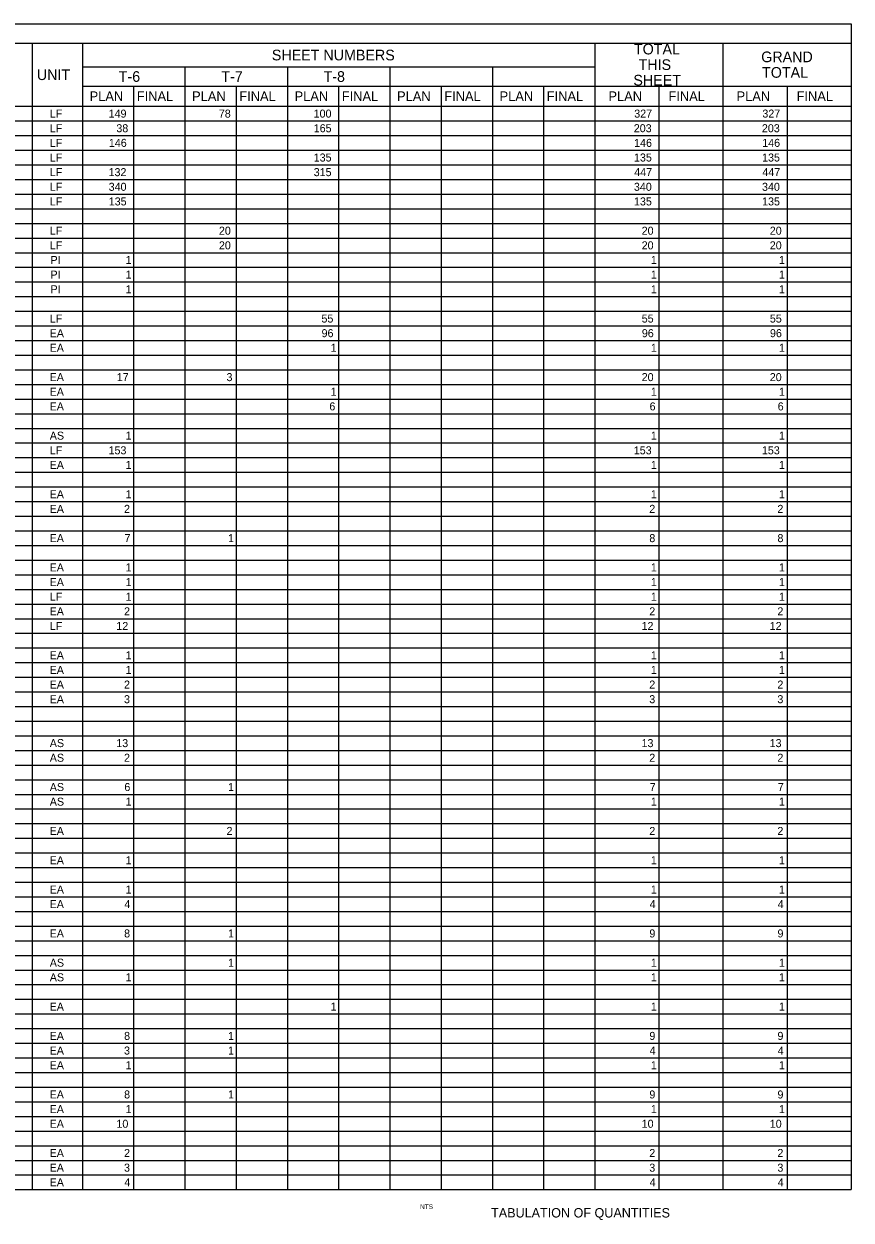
# Model space of a CAD drawing. Extents: x 0.1 to 15.3, y -0.2 to 9.6.
# Drawn here: x 8.54 to 15.31, y -0.16 to 9.64 of the extents above; entities that cross this region are included whole.
import ezdxf

# ---------------------------------------------------------------- set-up
doc = ezdxf.new("R2010")
doc.units = 0
for name, color, linetype in [('Default', 7, 'Continuous'), ('SumBoxBorder_dp', 7, 'Continuous'), ('SumBoxLines_dp', 7, 'Continuous'), ('SumBoxLinesMin_dp', 7, 'Continuous'), ('TextLabel', 7, 'Continuous'), ('TextMisc', 7, 'Continuous')]:
    doc.layers.add(name, color=color, linetype=linetype)

msp = doc.modelspace()

# ---------------------------------------------------------------- linework, layer by layer
at = {"layer": 'SumBoxBorder_dp'}
for p, q in [((0.1195, 9.6404), (15.3145, 9.6404)), ((15.3145, 9.6404), (15.3145, 0.0854)), ((0.1195, 9.4829), (15.3145, 9.4829)), ((0.1195, 9.4829), (15.3145, 9.4829)), ((0.1195, 0.0854), (15.3145, 0.0854))]:
    msp.add_line(p, q, dxfattribs=at)
at = {"layer": 'SumBoxLines_dp'}
for p, q in [((8.602, 9.4829), (8.602, 4.4054)), ((8.602, 9.4829), (8.602, 0.0854)), ((9.0145, 9.4829), (9.0145, 9.1304)), ((9.0145, 9.4829), (9.0145, 0.0854)), ((13.2145, 9.4829), (13.2145, 0.0854)), ((13.2145, 9.4829), (13.2145, 0.0854)), ((14.2645, 9.4829), (14.2645, 0.0854)), ((9.0145, 9.2879), (13.2145, 9.2879)), ((9.0145, 9.2879), (13.2145, 9.2879)), ((9.8545, 9.2879), (9.8545, 0.0854)), ((9.8545, 9.2879), (9.8545, 0.0854)), ((10.6945, 9.2879), (10.6945, 0.0854)), ((10.6945, 9.2879), (10.6945, 9.1304)), ((11.5345, 9.2879), (11.5345, 0.0854)), ((11.5345, 9.2879), (11.5345, 0.0854)), ((12.3745, 9.2879), (12.3745, 8.8454)), ((12.3745, 9.2879), (12.3745, 0.0854)), ((9.0145, 9.1304), (15.3145, 9.1304)), ((11.5345, 9.1304), (15.3145, 9.1304)), ((14.2645, 9.1304), (14.2645, 8.8454)), ((0.1195, 8.9654), (15.3145, 8.9654)), ((0.1195, 8.9654), (15.3145, 8.9654)), ((9.0145, 8.9654), (9.0145, 0.0854)), ((10.6945, 8.9654), (10.6945, 0.0854)), ((12.3745, 8.7254), (12.3745, 0.0854)), ((14.2645, 8.7254), (14.2645, 0.0854)), ((8.602, 4.2854), (8.602, 0.0854))]:
    msp.add_line(p, q, dxfattribs=at)
at = {"layer": 'SumBoxLinesMin_dp'}
for p, q in [((9.4345, 9.1304), (9.4345, 8.8454)), ((9.4345, 9.1304), (9.4345, 0.0854)), ((10.2745, 9.1304), (10.2745, 8.8454)), ((10.2745, 9.1304), (10.2745, 0.0854)), ((10.6945, 9.1304), (10.6945, 8.9654)), ((11.1145, 9.1304), (11.1145, 8.8454)), ((11.1145, 9.1304), (11.1145, 0.0854)), ((11.9545, 9.1304), (11.9545, 0.0854)), ((11.9545, 9.1304), (11.9545, 0.0854)), ((12.7945, 9.1304), (12.7945, 0.0854)), ((12.7945, 9.1304), (12.7945, 0.0854)), ((13.7395, 9.1304), (13.7395, 0.0854)), ((13.7395, 9.1304), (13.7395, 0.0854)), ((14.7895, 9.1304), (14.7895, 0.0854)), ((14.7895, 9.1304), (14.7895, 0.0854)), ((0.1195, 8.8454), (15.3145, 8.8454)), ((0.1195, 8.8454), (15.3145, 8.8454)), ((12.3745, 8.8454), (12.3745, 8.7254)), ((14.2645, 8.8454), (14.2645, 8.7254)), ((0.1195, 8.7254), (15.3145, 8.7254)), ((0.1195, 8.7254), (15.3145, 8.7254)), ((9.4345, 8.7254), (9.4345, 0.0854)), ((10.2745, 8.7254), (10.2745, 0.0854)), ((11.1145, 8.7254), (11.1145, 0.0854)), ((0.1195, 8.6054), (15.3145, 8.6054)), ((0.1195, 8.6054), (15.3145, 8.6054)), ((0.1195, 8.4854), (15.3145, 8.4854)), ((0.1195, 8.4854), (15.3145, 8.4854)), ((0.1195, 8.3654), (15.3145, 8.3654)), ((0.1195, 8.3654), (15.3145, 8.3654)), ((0.1195, 8.2454), (15.3145, 8.2454)), ((0.1195, 8.2454), (15.3145, 8.2454)), ((0.1195, 8.1254), (15.3145, 8.1254)), ((0.1195, 8.1254), (15.3145, 8.1254)), ((0.1195, 8.0054), (15.3145, 8.0054)), ((0.1195, 8.0054), (15.3145, 8.0054)), ((0.1195, 7.8854), (15.3145, 7.8854)), ((0.1195, 7.8854), (15.3145, 7.8854)), ((0.1195, 7.7654), (15.3145, 7.7654)), ((0.1195, 7.7654), (15.3145, 7.7654)), ((0.1195, 7.6454), (15.3145, 7.6454)), ((0.1195, 7.6454), (15.3145, 7.6454)), ((0.1195, 7.5254), (15.3145, 7.5254)), ((0.1195, 7.5254), (15.3145, 7.5254)), ((0.1195, 7.4054), (15.3145, 7.4054)), ((0.1195, 7.4054), (15.3145, 7.4054)), ((0.1195, 7.2854), (15.3145, 7.2854)), ((0.1195, 7.2854), (15.3145, 7.2854)), ((0.1195, 7.1654), (15.3145, 7.1654)), ((0.1195, 7.1654), (15.3145, 7.1654)), ((0.1195, 7.0454), (15.3145, 7.0454)), ((0.1195, 7.0454), (15.3145, 7.0454)), ((0.1195, 6.9254), (15.3145, 6.9254)), ((0.1195, 6.9254), (15.3145, 6.9254)), ((0.1195, 6.8054), (15.3145, 6.8054)), ((0.1195, 6.8054), (15.3145, 6.8054)), ((0.1195, 6.6854), (15.3145, 6.6854)), ((0.1195, 6.6854), (15.3145, 6.6854)), ((0.1195, 6.5654), (15.3145, 6.5654)), ((0.1195, 6.5654), (15.3145, 6.5654)), ((0.1195, 6.4454), (15.3145, 6.4454)), ((0.1195, 6.4454), (15.3145, 6.4454)), ((0.1195, 6.3254), (15.3145, 6.3254)), ((0.1195, 6.3254), (15.3145, 6.3254)), ((0.1195, 6.2054), (15.3145, 6.2054)), ((0.1195, 6.2054), (15.3145, 6.2054)), ((0.1195, 6.0854), (15.3145, 6.0854)), ((0.1195, 6.0854), (15.3145, 6.0854)), ((0.1195, 5.9654), (15.3145, 5.9654)), ((0.1195, 5.9654), (15.3145, 5.9654)), ((0.1195, 5.8454), (15.3145, 5.8454)), ((0.1195, 5.8454), (15.3145, 5.8454)), ((0.1195, 5.7254), (15.3145, 5.7254)), ((0.1195, 5.7254), (15.3145, 5.7254)), ((0.1195, 5.6054), (15.3145, 5.6054)), ((0.1195, 5.6054), (15.3145, 5.6054)), ((0.1195, 5.4854), (15.3145, 5.4854)), ((0.1195, 5.4854), (15.3145, 5.4854)), ((0.1195, 5.3654), (15.3145, 5.3654)), ((0.1195, 5.3654), (15.3145, 5.3654)), ((0.1195, 5.2454), (15.3145, 5.2454)), ((0.1195, 5.2454), (15.3145, 5.2454)), ((0.1195, 5.1254), (15.3145, 5.1254)), ((0.1195, 5.1254), (15.3145, 5.1254)), ((0.1195, 5.0054), (15.3145, 5.0054)), ((0.1195, 5.0054), (15.3145, 5.0054)), ((0.1195, 4.8854), (15.3145, 4.8854)), ((0.1195, 4.8854), (15.3145, 4.8854)), ((0.1195, 4.7654), (15.3145, 4.7654)), ((0.1195, 4.7654), (15.3145, 4.7654)), ((0.1195, 4.6454), (15.3145, 4.6454)), ((0.1195, 4.6454), (15.3145, 4.6454)), ((0.1195, 4.5254), (15.3145, 4.5254)), ((0.1195, 4.5254), (15.3145, 4.5254)), ((0.1195, 4.4054), (15.3145, 4.4054)), ((0.1195, 4.4054), (15.3145, 4.4054)), ((0.1195, 4.2854), (15.3145, 4.2854)), ((8.602, 4.2854), (15.3145, 4.2854)), ((0.1195, 4.1654), (15.3145, 4.1654)), ((0.1195, 4.1654), (15.3145, 4.1654)), ((0.1195, 4.0454), (15.3145, 4.0454)), ((0.1195, 4.0454), (15.3145, 4.0454)), ((0.1195, 3.9254), (15.3145, 3.9254)), ((0.1195, 3.9254), (15.3145, 3.9254)), ((0.1195, 3.8054), (15.3145, 3.8054)), ((0.1195, 3.8054), (15.3145, 3.8054)), ((0.1195, 3.6854), (15.3145, 3.6854)), ((0.1195, 3.6854), (15.3145, 3.6854)), ((0.1195, 3.5654), (15.3145, 3.5654)), ((0.1195, 3.5654), (15.3145, 3.5654)), ((0.1195, 3.4454), (15.3145, 3.4454)), ((0.1195, 3.4454), (15.3145, 3.4454)), ((0.1195, 3.3254), (15.3145, 3.3254)), ((0.1195, 3.3254), (15.3145, 3.3254)), ((0.1195, 3.2054), (15.3145, 3.2054)), ((0.1195, 3.2054), (15.3145, 3.2054)), ((0.1195, 3.0854), (15.3145, 3.0854)), ((0.1195, 3.0854), (15.3145, 3.0854)), ((0.1195, 2.9654), (15.3145, 2.9654)), ((0.1195, 2.9654), (15.3145, 2.9654)), ((0.1195, 2.8454), (15.3145, 2.8454)), ((0.1195, 2.8454), (15.3145, 2.8454)), ((0.1195, 2.7254), (15.3145, 2.7254)), ((0.1195, 2.7254), (15.3145, 2.7254)), ((0.1195, 2.6054), (15.3145, 2.6054)), ((0.1195, 2.6054), (15.3145, 2.6054)), ((0.1195, 2.4854), (15.3145, 2.4854)), ((0.1195, 2.4854), (15.3145, 2.4854)), ((0.1195, 2.3654), (15.3145, 2.3654)), ((0.1195, 2.3654), (15.3145, 2.3654)), ((0.1195, 2.2454), (15.3145, 2.2454)), ((0.1195, 2.2454), (15.3145, 2.2454)), ((0.1195, 2.1254), (15.3145, 2.1254)), ((9.0145, 2.1254), (9.4345, 2.1254)), ((9.8545, 2.1254), (10.2745, 2.1254)), ((13.2145, 2.1254), (13.7395, 2.1254)), ((14.2645, 2.1254), (14.7895, 2.1254)), ((0.1195, 2.0054), (15.3145, 2.0054)), ((9.0145, 2.0054), (9.4345, 2.0054)), ((9.8545, 2.0054), (10.2745, 2.0054)), ((13.2145, 2.0054), (13.7395, 2.0054)), ((14.2645, 2.0054), (14.7895, 2.0054)), ((0.1195, 1.8854), (15.3145, 1.8854)), ((9.0145, 1.8854), (9.4345, 1.8854)), ((9.8545, 1.8854), (10.2745, 1.8854)), ((13.2145, 1.8854), (13.7395, 1.8854)), ((14.2645, 1.8854), (14.7895, 1.8854)), ((0.1195, 1.7654), (15.3145, 1.7654)), ((9.0145, 1.7654), (9.4345, 1.7654)), ((9.8545, 1.7654), (10.2745, 1.7654)), ((13.2145, 1.7654), (13.7395, 1.7654)), ((14.2645, 1.7654), (14.7895, 1.7654)), ((0.1195, 1.6454), (15.3145, 1.6454)), ((9.0145, 1.6454), (9.4345, 1.6454)), ((9.8545, 1.6454), (10.2745, 1.6454)), ((13.2145, 1.6454), (13.7395, 1.6454)), ((14.2645, 1.6454), (14.7895, 1.6454)), ((0.1195, 1.5254), (15.3145, 1.5254)), ((9.0145, 1.5254), (9.4345, 1.5254)), ((9.8545, 1.5254), (10.2745, 1.5254)), ((13.2145, 1.5254), (13.7395, 1.5254)), ((14.2645, 1.5254), (14.7895, 1.5254)), ((0.1195, 1.4054), (15.3145, 1.4054)), ((9.0145, 1.4054), (9.4345, 1.4054)), ((9.8545, 1.4054), (10.2745, 1.4054)), ((13.2145, 1.4054), (13.7395, 1.4054)), ((14.2645, 1.4054), (14.7895, 1.4054)), ((0.1195, 1.2854), (15.3145, 1.2854)), ((9.0145, 1.2854), (9.4345, 1.2854)), ((9.8545, 1.2854), (10.2745, 1.2854)), ((13.2145, 1.2854), (13.7395, 1.2854)), ((14.2645, 1.2854), (14.7895, 1.2854)), ((0.1195, 1.1654), (15.3145, 1.1654)), ((9.0145, 1.1654), (9.4345, 1.1654)), ((9.8545, 1.1654), (10.2745, 1.1654)), ((13.2145, 1.1654), (13.7395, 1.1654)), ((14.2645, 1.1654), (14.7895, 1.1654)), ((0.1195, 1.0454), (15.3145, 1.0454)), ((9.0145, 1.0454), (9.4345, 1.0454)), ((9.8545, 1.0454), (10.2745, 1.0454)), ((13.2145, 1.0454), (13.7395, 1.0454)), ((14.2645, 1.0454), (14.7895, 1.0454)), ((0.1195, 0.9254), (15.3145, 0.9254)), ((9.0145, 0.9254), (9.4345, 0.9254)), ((9.8545, 0.9254), (10.2745, 0.9254)), ((13.2145, 0.9254), (13.7395, 0.9254)), ((14.2645, 0.9254), (14.7895, 0.9254)), ((0.1195, 0.8054), (15.3145, 0.8054)), ((9.0145, 0.8054), (9.4345, 0.8054)), ((9.8545, 0.8054), (10.2745, 0.8054)), ((13.2145, 0.8054), (13.7395, 0.8054)), ((14.2645, 0.8054), (14.7895, 0.8054)), ((0.1195, 0.6854), (15.3145, 0.6854)), ((9.0145, 0.6854), (9.4345, 0.6854)), ((9.8545, 0.6854), (10.2745, 0.6854)), ((13.2145, 0.6854), (13.7395, 0.6854)), ((14.2645, 0.6854), (14.7895, 0.6854)), ((0.1195, 0.5654), (15.3145, 0.5654)), ((9.0145, 0.5654), (9.4345, 0.5654)), ((9.8545, 0.5654), (10.2745, 0.5654)), ((13.2145, 0.5654), (13.7395, 0.5654)), ((14.2645, 0.5654), (14.7895, 0.5654)), ((0.1195, 0.4454), (15.3145, 0.4454)), ((9.0145, 0.4454), (9.4345, 0.4454)), ((9.8545, 0.4454), (10.2745, 0.4454)), ((13.2145, 0.4454), (13.7395, 0.4454)), ((14.2645, 0.4454), (14.7895, 0.4454)), ((0.1195, 0.3254), (15.3145, 0.3254)), ((9.0145, 0.3254), (9.4345, 0.3254)), ((9.8545, 0.3254), (10.2745, 0.3254)), ((13.2145, 0.3254), (13.7395, 0.3254)), ((14.2645, 0.3254), (14.7895, 0.3254)), ((0.1195, 0.2054), (15.3145, 0.2054)), ((13.2145, 0.2054), (13.7395, 0.2054)), ((14.2645, 0.2054), (14.7895, 0.2054))]:
    msp.add_line(p, q, dxfattribs=at)

# ---------------------------------------------------------------- texts
at = {"layer": 'Default'}
msp.add_text('TABULATION OF QUANTITIES', height=0.0771, dxfattribs=at).set_placement((12.364, -0.143))
at = {"layer": 'TextLabel'}
for s, height, p in [('SHEET NUMBERS', 0.0875, (10.567, 9.3417)), ('TOTAL', 0.0875, (13.5349, 9.3904)), ('GRAND', 0.0875, (14.5781, 9.3267)), ('THIS', 0.0875, (13.5731, 9.2629)), ('UNIT', 0.0875, (8.6411, 9.1804)), ('T-6', 0.0875, (9.3123, 9.1654)), ('T-7', 0.0875, (10.153, 9.1654)), ('T-8', 0.0875, (10.9908, 9.1654)), ('SHEET', 0.0875, (13.53, 9.1354)), ('TOTAL', 0.0875, (14.5849, 9.1992)), ('PLAN', 0.07875, (9.0735, 9.0085)), ('FINAL', 0.07875, (9.4604, 9.0085)), ('PLAN', 0.07875, (9.9135, 9.0085)), ('FINAL', 0.07875, (10.3004, 9.0085)), ('PLAN', 0.07875, (10.7535, 9.0085)), ('FINAL', 0.07875, (11.1404, 9.0085)), ('PLAN', 0.07875, (11.5935, 9.0085)), ('FINAL', 0.07875, (11.9804, 9.0085)), ('PLAN', 0.07875, (12.4335, 9.0085)), ('FINAL', 0.07875, (12.8204, 9.0085)), ('PLAN', 0.07875, (13.326, 9.0085)), ('FINAL', 0.07875, (13.8179, 9.0085)), ('PLAN', 0.07875, (14.376, 9.0085)), ('FINAL', 0.07875, (14.8679, 9.0085)), ('LF', 0.06563, (8.7478, 8.8726)), ('149', 0.06563, (9.2293, 8.8726)), ('78', 0.06563, (10.1325, 8.8726)), ('100', 0.06563, (10.9096, 8.8726)), ('327', 0.06563, (13.5373, 8.8726)), ('327', 0.06563, (14.5873, 8.8726)), ('LF', 0.06563, (8.7478, 8.7526)), ('38', 0.06563, (9.2925, 8.7526)), ('165', 0.06563, (10.9102, 8.7526)), ('203', 0.06563, (13.5335, 8.7526)), ('203', 0.06563, (14.5835, 8.7526)), ('LF', 0.06563, (8.7478, 8.6326)), ('146', 0.06563, (9.2312, 8.6326)), ('146', 0.06563, (13.5362, 8.6326)), ('146', 0.06563, (14.5862, 8.6326)), ('LF', 0.06563, (8.7478, 8.5126)), ('135', 0.06563, (10.9102, 8.5126)), ('135', 0.06563, (13.5352, 8.5126)), ('135', 0.06563, (14.5852, 8.5126)), ('LF', 0.06563, (8.7478, 8.3926)), ('132', 0.06563, (9.2286, 8.3926)), ('315', 0.06563, (10.9102, 8.3926)), ('447', 0.06563, (13.5373, 8.3926)), ('447', 0.06563, (14.5873, 8.3926)), ('LF', 0.06563, (8.7478, 8.2726)), ('340', 0.06563, (9.2296, 8.2726)), ('340', 0.06563, (13.5346, 8.2726)), ('340', 0.06563, (14.5846, 8.2726)), ('LF', 0.06563, (8.7478, 8.1526)), ('135', 0.06563, (9.2302, 8.1526)), ('135', 0.06563, (13.5352, 8.1526)), ('135', 0.06563, (14.5852, 8.1526)), ('LF', 0.06563, (8.7478, 7.9126)), ('20', 0.06563, (10.1332, 7.9126)), ('20', 0.06563, (13.5982, 7.9126)), ('20', 0.06563, (14.6482, 7.9126)), ('LF', 0.06563, (8.7478, 7.7926)), ('20', 0.06563, (10.1332, 7.7926)), ('20', 0.06563, (13.5982, 7.7926)), ('20', 0.06563, (14.6482, 7.7926)), ('PI', 0.06563, (8.7528, 7.6726)), ('1', 0.0656, (9.3682, 7.6726)), ('1', 0.0656, (13.6732, 7.6726)), ('1', 0.0656, (14.7232, 7.6726)), ('PI', 0.06563, (8.7528, 7.5526)), ('1', 0.0656, (9.3682, 7.5526)), ('1', 0.0656, (13.6732, 7.5526)), ('1', 0.0656, (14.7232, 7.5526)), ('PI', 0.06563, (8.7528, 7.4326)), ('1', 0.0656, (9.3682, 7.4326)), ('1', 0.0656, (13.6732, 7.4326)), ('1', 0.0656, (14.7232, 7.4326)), ('LF', 0.06563, (8.7478, 7.1926)), ('55', 0.06563, (10.9737, 7.1926)), ('55', 0.06563, (13.5987, 7.1926)), ('55', 0.06563, (14.6487, 7.1926)), ('EA', 0.06563, (8.7457, 7.0726)), ('96', 0.06563, (10.9747, 7.0726)), ('96', 0.06563, (13.5997, 7.0726)), ('96', 0.06563, (14.6497, 7.0726)), ('EA', 0.06563, (8.7457, 6.9526)), ('1', 0.0656, (11.0482, 6.9526)), ('1', 0.0656, (13.6732, 6.9526)), ('1', 0.0656, (14.7232, 6.9526)), ('EA', 0.06563, (8.7457, 6.7126)), ('17', 0.06563, (9.2958, 6.7126)), ('3', 0.0656, (10.1955, 6.7126)), ('20', 0.06563, (13.5982, 6.7126)), ('20', 0.06563, (14.6482, 6.7126)), ('EA', 0.06563, (8.7457, 6.5926)), ('1', 0.0656, (11.0482, 6.5926)), ('1', 0.0656, (13.6732, 6.5926)), ('1', 0.0656, (14.7232, 6.5926)), ('EA', 0.06563, (8.7457, 6.4726)), ('6', 0.0656, (11.0382, 6.4726)), ('6', 0.0656, (13.6632, 6.4726)), ('6', 0.0656, (14.7132, 6.4726)), ('AS', 0.06563, (8.747, 6.2326)), ('1', 0.0656, (9.3682, 6.2326)), ('1', 0.0656, (13.6732, 6.2326)), ('1', 0.0656, (14.7232, 6.2326)), ('LF', 0.06563, (8.7478, 6.1126)), ('153', 0.06563, (9.2285, 6.1126)), ('153', 0.06563, (13.5335, 6.1126)), ('153', 0.06563, (14.5835, 6.1126)), ('EA', 0.06563, (8.7457, 5.9926)), ('1', 0.0656, (9.3682, 5.9926)), ('1', 0.0656, (13.6732, 5.9926)), ('1', 0.0656, (14.7232, 5.9926)), ('EA', 0.06563, (8.7457, 5.7526)), ('1', 0.0656, (9.3682, 5.7526)), ('1', 0.0656, (13.6732, 5.7526)), ('1', 0.0656, (14.7232, 5.7526)), ('EA', 0.06563, (8.7457, 5.6326)), ('2', 0.0656, (9.3556, 5.6326)), ('2', 0.0656, (13.6606, 5.6326)), ('2', 0.0656, (14.7106, 5.6326)), ('EA', 0.06563, (8.7457, 5.3926)), ('7', 0.0656, (9.3593, 5.3926)), ('1', 0.0656, (10.2082, 5.3926)), ('8', 0.0656, (13.6611, 5.3926)), ('8', 0.0656, (14.7111, 5.3926)), ('EA', 0.06563, (8.7457, 5.1526)), ('1', 0.0656, (9.3682, 5.1526)), ('1', 0.0656, (13.6732, 5.1526)), ('1', 0.0656, (14.7232, 5.1526)), ('EA', 0.06563, (8.7457, 5.0326)), ('1', 0.0656, (9.3682, 5.0326)), ('1', 0.0656, (13.6732, 5.0326)), ('1', 0.0656, (14.7232, 5.0326)), ('LF', 0.06563, (8.7478, 4.9126)), ('1', 0.0656, (9.3682, 4.9126)), ('1', 0.0656, (13.6732, 4.9126)), ('1', 0.0656, (14.7232, 4.9126)), ('EA', 0.06563, (8.7457, 4.7926)), ('2', 0.0656, (9.3556, 4.7926)), ('2', 0.0656, (13.6606, 4.7926)), ('2', 0.0656, (14.7106, 4.7926)), ('LF', 0.06563, (8.7478, 4.6726)), ('12', 0.06563, (9.2921, 4.6726)), ('12', 0.06563, (13.5971, 4.6726)), ('12', 0.06563, (14.6471, 4.6726)), ('EA', 0.06563, (8.7457, 4.4326)), ('1', 0.0656, (9.3682, 4.4326)), ('1', 0.0656, (13.6732, 4.4326)), ('1', 0.0656, (14.7232, 4.4326)), ('EA', 0.06563, (8.7457, 4.3126)), ('1', 0.0656, (9.3682, 4.3126)), ('1', 0.0656, (13.6732, 4.3126)), ('1', 0.0656, (14.7232, 4.3126)), ('EA', 0.06563, (8.7457, 4.1926)), ('2', 0.0656, (9.3556, 4.1926)), ('2', 0.0656, (13.6606, 4.1926)), ('2', 0.0656, (14.7106, 4.1926)), ('EA', 0.06563, (8.7457, 4.0726)), ('3', 0.0656, (9.3555, 4.0726)), ('3', 0.0656, (13.6605, 4.0726)), ('3', 0.0656, (14.7105, 4.0726)), ('AS', 0.06563, (8.747, 3.7126)), ('13', 0.06563, (9.292, 3.7126)), ('13', 0.06563, (13.597, 3.7126)), ('13', 0.06563, (14.647, 3.7126)), ('AS', 0.06563, (8.747, 3.5926)), ('2', 0.0656, (9.3556, 3.5926)), ('2', 0.0656, (13.6606, 3.5926)), ('2', 0.0656, (14.7106, 3.5926)), ('AS', 0.06563, (8.747, 3.3526)), ('6', 0.0656, (9.3582, 3.3526)), ('1', 0.0656, (10.2082, 3.3526)), ('7', 0.0656, (13.6643, 3.3526)), ('7', 0.0656, (14.7143, 3.3526)), ('AS', 0.06563, (8.747, 3.2326)), ('1', 0.0656, (9.3682, 3.2326)), ('1', 0.0656, (13.6732, 3.2326)), ('1', 0.0656, (14.7232, 3.2326)), ('EA', 0.06563, (8.7457, 2.9926)), ('2', 0.0656, (10.1956, 2.9926)), ('2', 0.0656, (13.6606, 2.9926)), ('2', 0.0656, (14.7106, 2.9926)), ('EA', 0.06563, (8.7457, 2.7526)), ('1', 0.0656, (9.3682, 2.7526)), ('1', 0.0656, (13.6732, 2.7526)), ('1', 0.0656, (14.7232, 2.7526)), ('EA', 0.06563, (8.7457, 2.5126)), ('1', 0.0656, (9.3682, 2.5126)), ('1', 0.0656, (13.6732, 2.5126)), ('1', 0.0656, (14.7232, 2.5126)), ('EA', 0.06563, (8.7457, 2.3926)), ('4', 0.0656, (9.3582, 2.3926)), ('4', 0.0656, (13.6632, 2.3926)), ('4', 0.0656, (14.7132, 2.3926)), ('EA', 0.06563, (8.7457, 2.1526)), ('8', 0.0656, (9.3561, 2.1526)), ('1', 0.0656, (10.2082, 2.1526)), ('9', 0.0656, (13.6613, 2.1526)), ('9', 0.0656, (14.7113, 2.1526)), ('AS', 0.06563, (8.747, 1.9126)), ('1', 0.0656, (10.2082, 1.9126)), ('1', 0.0656, (13.6732, 1.9126)), ('1', 0.0656, (14.7232, 1.9126)), ('AS', 0.06563, (8.747, 1.7926)), ('1', 0.0656, (9.3682, 1.7926)), ('1', 0.0656, (13.6732, 1.7926)), ('1', 0.0656, (14.7232, 1.7926)), ('EA', 0.06563, (8.7457, 1.5526)), ('1', 0.0656, (11.0482, 1.5526)), ('1', 0.0656, (13.6732, 1.5526)), ('1', 0.0656, (14.7232, 1.5526)), ('EA', 0.06563, (8.7457, 1.3126)), ('8', 0.0656, (9.3561, 1.3126)), ('1', 0.0656, (10.2082, 1.3126)), ('9', 0.0656, (13.6613, 1.3126)), ('9', 0.0656, (14.7113, 1.3126)), ('EA', 0.06563, (8.7457, 1.1926)), ('3', 0.0656, (9.3555, 1.1926)), ('1', 0.0656, (10.2082, 1.1926)), ('4', 0.0656, (13.6632, 1.1926)), ('4', 0.0656, (14.7132, 1.1926)), ('EA', 0.06563, (8.7457, 1.0726)), ('1', 0.0656, (9.3682, 1.0726)), ('1', 0.0656, (13.6732, 1.0726)), ('1', 0.0656, (14.7232, 1.0726)), ('EA', 0.06563, (8.7457, 0.8326)), ('8', 0.0656, (9.3561, 0.8326)), ('1', 0.0656, (10.2082, 0.8326)), ('9', 0.0656, (13.6613, 0.8326)), ('9', 0.0656, (14.7113, 0.8326)), ('EA', 0.06563, (8.7457, 0.7126)), ('1', 0.0656, (9.3682, 0.7126)), ('1', 0.0656, (13.6732, 0.7126)), ('1', 0.0656, (14.7232, 0.7126)), ('EA', 0.06563, (8.7457, 0.5926)), ('10', 0.06563, (9.2932, 0.5926)), ('10', 0.06563, (13.5982, 0.5926)), ('10', 0.06563, (14.6482, 0.5926)), ('EA', 0.06563, (8.7457, 0.3526)), ('2', 0.0656, (9.3556, 0.3526)), ('2', 0.0656, (13.6606, 0.3526)), ('2', 0.0656, (14.7106, 0.3526)), ('EA', 0.06563, (8.7457, 0.2326)), ('3', 0.0656, (9.3555, 0.2326)), ('3', 0.0656, (13.6605, 0.2326)), ('3', 0.0656, (14.7105, 0.2326)), ('EA', 0.06563, (8.7457, 0.1126)), ('4', 0.0656, (9.3582, 0.1126)), ('4', 0.0656, (13.6632, 0.1126)), ('4', 0.0656, (14.7132, 0.1126))]:
    msp.add_text(s, height=height, dxfattribs=at).set_placement(p)
at = {"layer": 'TextMisc'}
msp.add_text('NTS', height=0.03855, dxfattribs=at).set_placement((11.7818, -0.0737))

doc.saveas('drawing.dxf')
